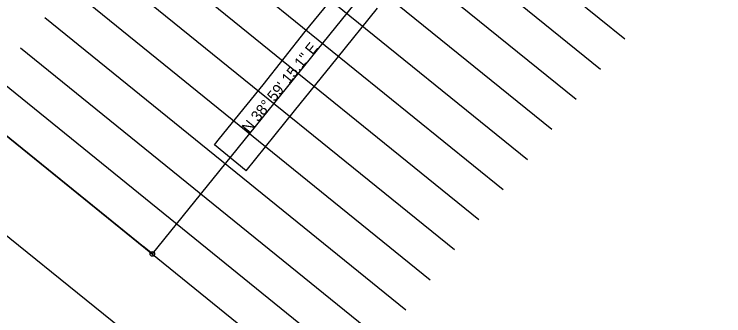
# Model space of a CAD drawing. Extents: x 2292992 to 2295123, y 892701 to 896230.
# Drawn here: x 2293381.5 to 2293840.1, y 892998.4 to 893193.3 of the extents above; entities that cross this region are included whole.
import ezdxf

# ---------------------------------------------------------------- set-up
doc = ezdxf.new("R2010")
doc.units = 0
for name, color, linetype in [('Prop EOT', 7, 'Continuous'), ('Prop Horizontal Alignment', 7, 'Continuous'), ('Prop Horizontal Alignment Direction Label', 7, 'Continuous'), ('Prop Horizontal Alignment Station Label', 7, 'Continuous'), ('Prop Horizontal Alignment Tick Large', 7, 'Continuous'), ('Prop Horizontal Alignment Tick Small', 7, 'Continuous'), ('Scratch_Level_3', 7, 'Continuous'), ('Scratch_Level_4', 7, 'Continuous'), ('Sheet Layout Plan Border', 7, 'Continuous')]:
    doc.layers.add(name, color=color, linetype=linetype)

msp = doc.modelspace()

# ---------------------------------------------------------------- linework, layer by layer
at = {"layer": 'Prop EOT'}
msp.add_line((2293531.51, 893092.16), (2293510.93, 893108.82), dxfattribs=at)
for points in [[(2293510.93, 893108.82), (2293514.29, 893112.95), (2293542.35, 893147.72), (2293569.63, 893181.99), (2293595.62, 893213.95)], [(2293531.53, 893092.15), (2293562.71, 893130.72), (2293590.2, 893164.83), (2293616.32, 893197.2)]]:
    msp.add_lwpolyline(points, dxfattribs=at)
at = {"layer": 'Prop Horizontal Alignment'}
msp.add_line((2293470.8, 893038.37), (2293640.91, 893248.53), dxfattribs=at)
at = {"layer": 'Prop Horizontal Alignment Station Label'}
msp.add_line((2293469.64, 893039.32), (2293304.11, 893173.3), dxfattribs=at)
msp.add_circle((2293470.8, 893038.37), 1.5, dxfattribs=at)
at = {"layer": 'Prop Horizontal Alignment Tick Large'}
msp.add_line((2293470.8, 893038.37), (2293464.59, 893043.41), dxfattribs=at)
at = {"layer": 'Prop Horizontal Alignment Tick Small'}
msp.add_line((2293533.72, 893116.1), (2293529.83, 893119.25), dxfattribs=at)
at = {"layer": 'Scratch_Level_3'}
msp.add_line((2293470.8, 893038.37), (2293640.91, 893248.53), dxfattribs=at)
at = {"layer": 'Scratch_Level_4'}
for p, q in [((2293542.89, 893365.87), (2293776.19, 893177.26)), ((2293527.22, 893346.49), (2293760.42, 893157.76)), ((2293511.5, 893327.07), (2293744.68, 893138.32)), ((2293495.77, 893307.63), (2293728.96, 893118.89)), ((2293480.04, 893288.2), (2293713.23, 893099.46)), ((2293464.31, 893268.77), (2293697.5, 893080.03)), ((2293448.58, 893249.34), (2293681.77, 893060.59)), ((2293432.85, 893229.91), (2293666.04, 893041.16)), ((2293417.13, 893210.47), (2293650.31, 893021.73)), ((2293401.4, 893191.04), (2293634.58, 893002.3)), ((2293385.67, 893171.61), (2293618.85, 892982.86)), ((2293369.94, 893152.18), (2293603.12, 892963.43)), ((2293354.21, 893132.75), (2293587.4, 892944))]:
    msp.add_line(p, q, dxfattribs=at)
at = {"layer": 'Sheet Layout Plan Border'}
msp.add_lwpolyline([(2293808.88, 892701.06), (2294688.51, 893790.22), (2293871.64, 894449.94), (2292992.02, 893360.79)], close=True, dxfattribs=at)

# ---------------------------------------------------------------- texts
at = {"layer": 'Prop Horizontal Alignment Direction Label'}
msp.add_text('N 38%%d 59\' 15.1" E', height=7, rotation=51.0125, dxfattribs=at).set_placement((2293533.38, 893116))

doc.saveas('drawing.dxf')
